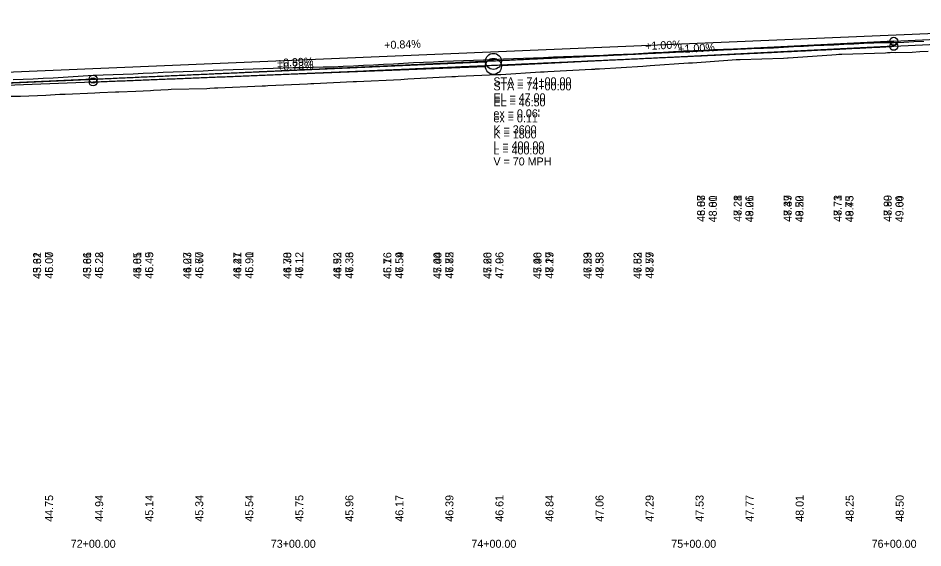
# Model space of a CAD drawing. Extents: x 3880794 to 3915434, y 287517 to 300173.
# Drawn here: x 3887700.8 to 3888152.9, y 296519.7 to 296784.4 of the extents above; entities that cross this region are included whole.
import ezdxf

# ---------------------------------------------------------------- set-up
doc = ezdxf.new("R2010")
doc.units = 0
for name, color, linetype in [('Level 1', 7, 'Continuous'), ('Level 2', 7, 'Continuous'), ('Level 30', 7, 'Continuous'), ('Level 31', 7, 'Continuous'), ('Level 32', 7, 'Continuous')]:
    doc.layers.add(name, color=color, linetype=linetype)

msp = doc.modelspace()

# ---------------------------------------------------------------- linework, layer by layer
at = {"layer": 'Level 1'}
for p, q in [((3888138.3, 296772.76), (3888338.3, 296782.76)), ((3888138.3, 296772.76), (3887942.29, 296762.96)), ((3888138.3, 296770.26), (3888238.3, 296775.26)), ((3888138.3, 296770.26), (3887942.29, 296760.46)), ((3887738.3, 296753.87), (3887934.3, 296762.58)), ((3887738.3, 296752.48), (3887934.3, 296760.1)), ((3887738.3, 296753.87), (3887492.29, 296742.93)), ((3887688.3, 296750.53), (3887738.3, 296752.48))]:
    msp.add_line(p, q, dxfattribs=at)
msp.add_lwpolyline([(3887697.12, 296745.32), (3887702.04, 296745.42), (3887714.66, 296745.94), (3887721.72, 296746.35), (3887724.3, 296746.31), (3887739.21, 296747.08), (3887741.66, 296747.2), (3887749.51, 296747.49), (3887750.4, 296747.52), (3887751.06, 296747.56), (3887759.69, 296747.85), (3887766.97, 296748.16), (3887768.46, 296748.28), (3887775.84, 296748.72), (3887777.36, 296748.82), (3887795.08, 296749.25), (3887796.6, 296749.34), (3887798.91, 296749.47), (3887800.57, 296749.56), (3887822.71, 296750.51), (3887823.96, 296750.58), (3887824.43, 296750.6), (3887825.53, 296750.65), (3887845.44, 296751.58), (3887847.04, 296751.65), (3887848.56, 296751.7), (3887868.23, 296752.62), (3887869.96, 296752.68), (3887892.01, 296753.76), (3887893.75, 296753.88), (3887895.56, 296753.95), (3887917.56, 296755.18), (3887919.28, 296755.24), (3887920.73, 296755.32), (3887940.36, 296756.12), (3887941.99, 296756.23), (3887961.81, 296757.48), (3887963.65, 296757.6), (3887965.44, 296757.76), (3887987.23, 296758.83), (3887988.95, 296758.93), (3887989.34, 296758.95), (3887991.26, 296759.06), (3888012.92, 296760.4), (3888014.73, 296760.51), (3888016.6, 296760.61), (3888035.69, 296762.05), (3888037.77, 296762.08), (3888057.52, 296763.59), (3888059.52, 296763.64), (3888061.55, 296763.75), (3888083.26, 296764.37), (3888085.22, 296764.5), (3888085.56, 296764.51), (3888107.44, 296766.03), (3888109.51, 296766.2), (3888110.82, 296766.29), (3888112.39, 296766.38), (3888134.15, 296767.07), (3888135.21, 296767.14), (3888135.68, 296767.21), (3888136.51, 296767.21), (3888137.15, 296767.26), (3888139.34, 296767.12), (3888147.45, 296767.36), (3888151.4, 296767.63), (3888155.49, 296767.82)], dxfattribs=at)
for centre in [(3887938.3, 296762.76), (3887938.3, 296760.26)]:
    msp.add_circle(centre, 4, dxfattribs=at)
for points in [[(3887738.3, 296753.87), (3887746.3, 296754.22), (3887754.3, 296754.58), (3887762.3, 296754.94), (3887770.3, 296755.3), (3887778.3, 296755.66), (3887786.3, 296756.02), (3887794.3, 296756.38), (3887802.3, 296756.74), (3887810.3, 296757.1), (3887818.3, 296757.47), (3887826.3, 296757.83), (3887834.3, 296758.2), (3887842.3, 296758.57), (3887850.3, 296758.93), (3887858.3, 296759.3), (3887866.3, 296759.67), (3887874.3, 296760.04), (3887882.3, 296760.41), (3887890.3, 296760.78), (3887898.3, 296761.16), (3887906.3, 296761.53), (3887914.3, 296761.91), (3887922.3, 296762.28), (3887930.3, 296762.66), (3887938.3, 296763.03), (3887946.3, 296763.41), (3887954.3, 296763.79), (3887962.3, 296764.17), (3887970.3, 296764.55), (3887978.3, 296764.93), (3887986.3, 296765.32), (3887994.3, 296765.7), (3888002.3, 296766.09), (3888010.3, 296766.47), (3888018.3, 296766.86), (3888026.3, 296767.24), (3888034.3, 296767.63), (3888042.3, 296768.02), (3888050.3, 296768.41), (3888058.3, 296768.8), (3888066.3, 296769.19), (3888074.3, 296769.59), (3888082.3, 296769.98), (3888090.3, 296770.37), (3888098.3, 296770.77), (3888106.3, 296771.16), (3888114.3, 296771.56), (3888122.3, 296771.96), (3888130.3, 296772.36), (3888138.3, 296772.76)], [(3887738.3, 296752.48), (3887746.3, 296752.79), (3887754.3, 296753.1), (3887762.3, 296753.42), (3887770.3, 296753.74), (3887778.3, 296754.06), (3887786.3, 296754.38), (3887794.3, 296754.7), (3887802.3, 296755.02), (3887810.3, 296755.35), (3887818.3, 296755.68), (3887826.3, 296756.01), (3887834.3, 296756.34), (3887842.3, 296756.67), (3887850.3, 296757.01), (3887858.3, 296757.35), (3887866.3, 296757.68), (3887874.3, 296758.02), (3887882.3, 296758.37), (3887890.3, 296758.71), (3887898.3, 296759.06), (3887906.3, 296759.4), (3887914.3, 296759.75), (3887922.3, 296760.1), (3887930.3, 296760.46), (3887938.3, 296760.81), (3887946.3, 296761.17), (3887954.3, 296761.53), (3887962.3, 296761.89), (3887970.3, 296762.25), (3887978.3, 296762.61), (3887986.3, 296762.98), (3887994.3, 296763.34), (3888002.3, 296763.71), (3888010.3, 296764.08), (3888018.3, 296764.46), (3888026.3, 296764.83), (3888034.3, 296765.21), (3888042.3, 296765.58), (3888050.3, 296765.96), (3888058.3, 296766.35), (3888066.3, 296766.73), (3888074.3, 296767.11), (3888082.3, 296767.5), (3888090.3, 296767.89), (3888098.3, 296768.28), (3888106.3, 296768.67), (3888114.3, 296769.06), (3888122.3, 296769.46), (3888130.3, 296769.86), (3888138.3, 296770.26)], [(3887238.3, 296733.14), (3887248.3, 296733.53), (3887258.3, 296733.91), (3887268.3, 296734.3), (3887278.3, 296734.69), (3887288.3, 296735.08), (3887298.3, 296735.47), (3887308.3, 296735.86), (3887318.3, 296736.26), (3887328.3, 296736.65), (3887338.3, 296737.05), (3887348.3, 296737.44), (3887358.3, 296737.84), (3887368.3, 296738.24), (3887378.3, 296738.64), (3887388.3, 296739.05), (3887398.3, 296739.45), (3887408.3, 296739.85), (3887418.3, 296740.26), (3887428.3, 296740.67), (3887438.3, 296741.07), (3887448.3, 296741.48), (3887458.3, 296741.89), (3887468.3, 296742.3), (3887478.3, 296742.72), (3887488.3, 296743.13), (3887498.3, 296743.55), (3887508.3, 296743.96), (3887518.3, 296744.38), (3887528.3, 296744.8), (3887538.3, 296745.22), (3887548.3, 296745.64), (3887558.3, 296746.06), (3887568.3, 296746.49), (3887578.3, 296746.91), (3887588.3, 296747.34), (3887598.3, 296747.76), (3887608.3, 296748.19), (3887618.3, 296748.62), (3887628.3, 296749.05), (3887638.3, 296749.48), (3887648.3, 296749.92), (3887658.3, 296750.35), (3887668.3, 296750.79), (3887678.3, 296751.22), (3887688.3, 296751.66), (3887698.3, 296752.1), (3887708.3, 296752.54), (3887718.3, 296752.98), (3887728.3, 296753.42), (3887738.3, 296753.87)]]:
    msp.add_spline(points, degree=3, dxfattribs=at)
at = {"layer": 'Level 2'}
msp.add_line((3886763.3, 296718.25), (3888338.3, 296784.36), dxfattribs=at)
for points in [[(3888038.3, 296768.16), (3888043.3, 296768.39), (3888048.3, 296768.61), (3888053.3, 296768.84), (3888058.3, 296769.01), (3888063.3, 296769.15), (3888068.3, 296769.28), (3888073.3, 296769.41), (3888078.3, 296769.59), (3888083.3, 296769.85), (3888088.3, 296770.11), (3888093.3, 296770.37), (3888098.3, 296770.63), (3888103.3, 296770.85), (3888108.3, 296771.07), (3888113.3, 296771.3), (3888118.3, 296771.53), (3888123.3, 296771.8), (3888128.3, 296771.95), (3888133.3, 296772.1), (3888138.3, 296772.25), (3888143.3, 296772.37), (3888148.3, 296772.61), (3888153.3, 296772.86)], [(3887698.3, 296753.66), (3887703.3, 296753.88), (3887708.3, 296754.1), (3887713.3, 296754.31), (3887718.3, 296754.53), (3887723.3, 296754.85), (3887728.3, 296755.17), (3887733.3, 296755.49), (3887738.3, 296755.8), (3887743.3, 296755.98), (3887748.3, 296756.17), (3887753.3, 296756.35), (3887758.3, 296756.54), (3887763.3, 296756.81), (3887768.3, 296757.03), (3887773.3, 296757.27), (3887778.3, 296757.5), (3887783.3, 296757.74), (3887788.3, 296757.9), (3887793.3, 296758.09), (3887798.3, 296758.28), (3887803.3, 296758.46), (3887808.3, 296758.65), (3887813.3, 296758.8), (3887818.3, 296758.98), (3887823.3, 296759.17), (3887828.3, 296759.35), (3887833.3, 296759.54), (3887838.3, 296759.67), (3887843.3, 296759.76), (3887848.3, 296759.86), (3887853.3, 296759.96), (3887858.3, 296760.08), (3887863.3, 296760.34), (3887868.3, 296760.57), (3887873.3, 296760.79), (3887878.3, 296761.02), (3887883.3, 296761.28), (3887888.3, 296761.57), (3887893.3, 296761.84), (3887898.3, 296762.1), (3887903.3, 296762.37), (3887908.3, 296762.57), (3887913.3, 296762.77), (3887918.3, 296762.97), (3887923.3, 296763.17), (3887928.3, 296763.37), (3887933.3, 296763.54), (3887938.3, 296763.74), (3887943.3, 296763.95), (3887948.3, 296764.15), (3887953.3, 296764.35), (3887958.3, 296764.58), (3887963.3, 296764.76), (3887968.3, 296764.94), (3887973.3, 296765.12), (3887978.3, 296765.3), (3887983.3, 296765.5), (3887988.3, 296765.71), (3887993.3, 296765.92), (3887998.3, 296766.14), (3888003.3, 296766.31), (3888008.3, 296766.59), (3888013.3, 296766.86), (3888018.3, 296767.14), (3888023.3, 296767.41), (3888028.3, 296767.67), (3888033.3, 296767.93), (3888038.3, 296768.16)]]:
    msp.add_lwpolyline(points, dxfattribs=at)
at = {"layer": 'Level 31'}
for centre in [(3888138.3, 296772.76), (3888138.3, 296770.26), (3887738.3, 296753.87), (3887738.3, 296753.87), (3887738.3, 296752.48)]:
    msp.add_circle(centre, 2, dxfattribs=at)

# ---------------------------------------------------------------- texts
at = {"layer": 'Level 2'}
for s, rotation, p in [('+0.84%', 2.4036, (3887883.8, 296768.85)), ('48.80', 90, (3888049.9, 296682.34)), ('49.01', 90, (3888068.18, 296682.34)), ('49.22', 90, (3888093.18, 296682.34)), ('49.43', 90, (3888118.18, 296682.34)), ('49.64', 90, (3888143.18, 296682.34)), ('46.07', 90, (3887718.3, 296654.19)), ('46.28', 90, (3887743.3, 296654.19)), ('46.49', 90, (3887768.3, 296654.19)), ('46.70', 90, (3887793.3, 296654.19)), ('46.91', 90, (3887818.3, 296654.19)), ('47.12', 90, (3887843.3, 296654.19)), ('47.33', 90, (3887868.3, 296654.19)), ('47.54', 90, (3887893.3, 296654.19)), ('47.75', 90, (3887918.3, 296654.19)), ('47.96', 90, (3887943.3, 296654.19)), ('48.17', 90, (3887968.3, 296654.19)), ('48.38', 90, (3887993.3, 296654.19)), ('48.59', 90, (3888018.3, 296654.19))]:
    msp.add_text(s, height=4, rotation=rotation, dxfattribs=at).set_placement(p)
for s, p in [('72+00.00', (3887727.09, 296519.76)), ('73+00.00', (3887827.05, 296519.76)), ('74+00.00', (3887927.27, 296519.76)), ('75+00.00', (3888027.15, 296519.76)), ('76+00.00', (3888127.27, 296519.76))]:
    msp.add_text(s, height=4, dxfattribs=at).set_placement(p)
at = {"layer": 'Level 30'}
for s, p in [('46.87', (3888044.01, 296682.58)), ('47.21', (3888062.3, 296682.58)), ('47.39', (3888087.3, 296682.58)), ('47.73', (3888112.3, 296682.58)), ('47.89', (3888137.3, 296682.58)), ('43.62', (3887712.3, 296654.04)), ('43.86', (3887737.3, 296654.04)), ('44.05', (3887762.3, 296654.04)), ('44.27', (3887787.3, 296654.04)), ('44.47', (3887812.3, 296654.04)), ('44.70', (3887837.3, 296654.04)), ('44.93', (3887862.3, 296654.04)), ('45.16', (3887887.3, 296654.04)), ('45.44', (3887912.3, 296654.04)), ('45.66', (3887937.3, 296654.04)), ('45.96', (3887962.3, 296654.04)), ('46.23', (3887987.3, 296654.04)), ('46.53', (3888012.3, 296654.04))]:
    msp.add_text(s, height=4, rotation=90, dxfattribs=at).set_placement(p)
for s, p in [('72+00.00', (3887727.09, 296519.76)), ('72+00.00', (3887727.09, 296519.76)), ('72+00.00', (3887727.09, 296519.76)), ('73+00.00', (3887827.05, 296519.76)), ('73+00.00', (3887827.05, 296519.76)), ('73+00.00', (3887827.05, 296519.76)), ('74+00.00', (3887927.27, 296519.76)), ('74+00.00', (3887927.27, 296519.76)), ('74+00.00', (3887927.27, 296519.76)), ('75+00.00', (3888027.15, 296519.76)), ('75+00.00', (3888027.15, 296519.76)), ('75+00.00', (3888027.15, 296519.76)), ('76+00.00', (3888127.27, 296519.76)), ('76+00.00', (3888127.27, 296519.76)), ('76+00.00', (3888127.27, 296519.76))]:
    msp.add_text(s, height=4, dxfattribs=at).set_placement(p)
at = {"layer": 'Level 31'}
for s, rotation, p in [('+1.00%', 2.8624, (3888014.22, 296768.38)), ('+1.00%', 2.8624, (3888030.74, 296766.88)), ('+0.89%', 2.5448, (3887830.16, 296759.95)), ('+0.78%', 2.227, (3887830.24, 296758.06)), ('48.01', 90, (3888049.9, 296682.34)), ('48.26', 90, (3888068.18, 296682.34)), ('48.50', 90, (3888093.18, 296682.34)), ('48.75', 90, (3888118.18, 296682.34)), ('49.00', 90, (3888143.18, 296682.34)), ('45.00', 90, (3887718.3, 296654.19)), ('45.22', 90, (3887743.3, 296654.19)), ('45.45', 90, (3887768.3, 296654.19)), ('45.67', 90, (3887793.3, 296654.19)), ('45.90', 90, (3887818.3, 296654.19)), ('46.12', 90, (3887843.3, 296654.19)), ('46.36', 90, (3887868.3, 296654.19)), ('46.59', 90, (3887893.3, 296654.19)), ('46.82', 90, (3887918.3, 296654.19)), ('47.06', 90, (3887943.3, 296654.19)), ('47.29', 90, (3887968.3, 296654.19)), ('47.53', 90, (3887993.3, 296654.19)), ('47.77', 90, (3888018.3, 296654.19)), ('44.75', 90, (3887718.3, 296532.76)), ('44.94', 90, (3887743.3, 296532.76)), ('45.14', 90, (3887768.3, 296532.76)), ('45.34', 90, (3887793.3, 296532.76)), ('45.54', 90, (3887818.3, 296532.76)), ('45.75', 90, (3887843.3, 296532.76)), ('45.96', 90, (3887868.3, 296532.76)), ('46.17', 90, (3887893.3, 296532.76)), ('46.39', 90, (3887918.3, 296532.76)), ('46.61', 90, (3887943.3, 296532.76)), ('46.84', 90, (3887968.3, 296532.76)), ('47.06', 90, (3887993.3, 296532.76)), ('47.29', 90, (3888018.3, 296532.76)), ('47.53', 90, (3888043.3, 296532.76)), ('47.77', 90, (3888068.3, 296532.76)), ('48.01', 90, (3888093.3, 296532.76)), ('48.25', 90, (3888118.3, 296532.76)), ('48.50', 90, (3888143.3, 296532.76))]:
    msp.add_text(s, height=4, rotation=rotation, dxfattribs=at).set_placement(p)
for s, p in [('STA = 74+00.00', (3887938.3, 296750.76)), ('STA = 74+00.00', (3887938.3, 296748.26)), ('EL = 47.00', (3887938.3, 296742.76)), ('EL = 46.50', (3887938.3, 296740.26)), ("ex = 0.06'", (3887938.3, 296734.76)), ("ex = 0.11'", (3887938.3, 296732.26)), ('K = 3600', (3887938.3, 296726.76)), ('K = 1800', (3887938.3, 296724.26)), ('L = 400.00', (3887938.3, 296718.76)), ('L = 400.00', (3887938.3, 296716.26)), ('V = 70 MPH', (3887938.3, 296710.76))]:
    msp.add_text(s, height=4, dxfattribs=at).set_placement(p)
at = {"layer": 'Level 32'}
for s, p in [('48.08', (3888044.01, 296682.58)), ('48.28', (3888062.3, 296682.58)), ('48.47', (3888087.3, 296682.58)), ('48.71', (3888112.3, 296682.58)), ('48.90', (3888137.3, 296682.58)), ('45.31', (3887712.3, 296654.04)), ('45.61', (3887737.3, 296654.04)), ('45.81', (3887762.3, 296654.04)), ('46.03', (3887787.3, 296654.04)), ('46.21', (3887812.3, 296654.04)), ('46.38', (3887837.3, 296654.04)), ('46.52', (3887862.3, 296654.04)), ('46.76', (3887887.3, 296654.04)), ('47.00', (3887912.3, 296654.04)), ('47.20', (3887937.3, 296654.04)), ('47.40', (3887962.3, 296654.04)), ('47.59', (3887987.3, 296654.04)), ('47.82', (3888012.3, 296654.04))]:
    msp.add_text(s, height=4, rotation=90, dxfattribs=at).set_placement(p)

doc.saveas('drawing.dxf')
